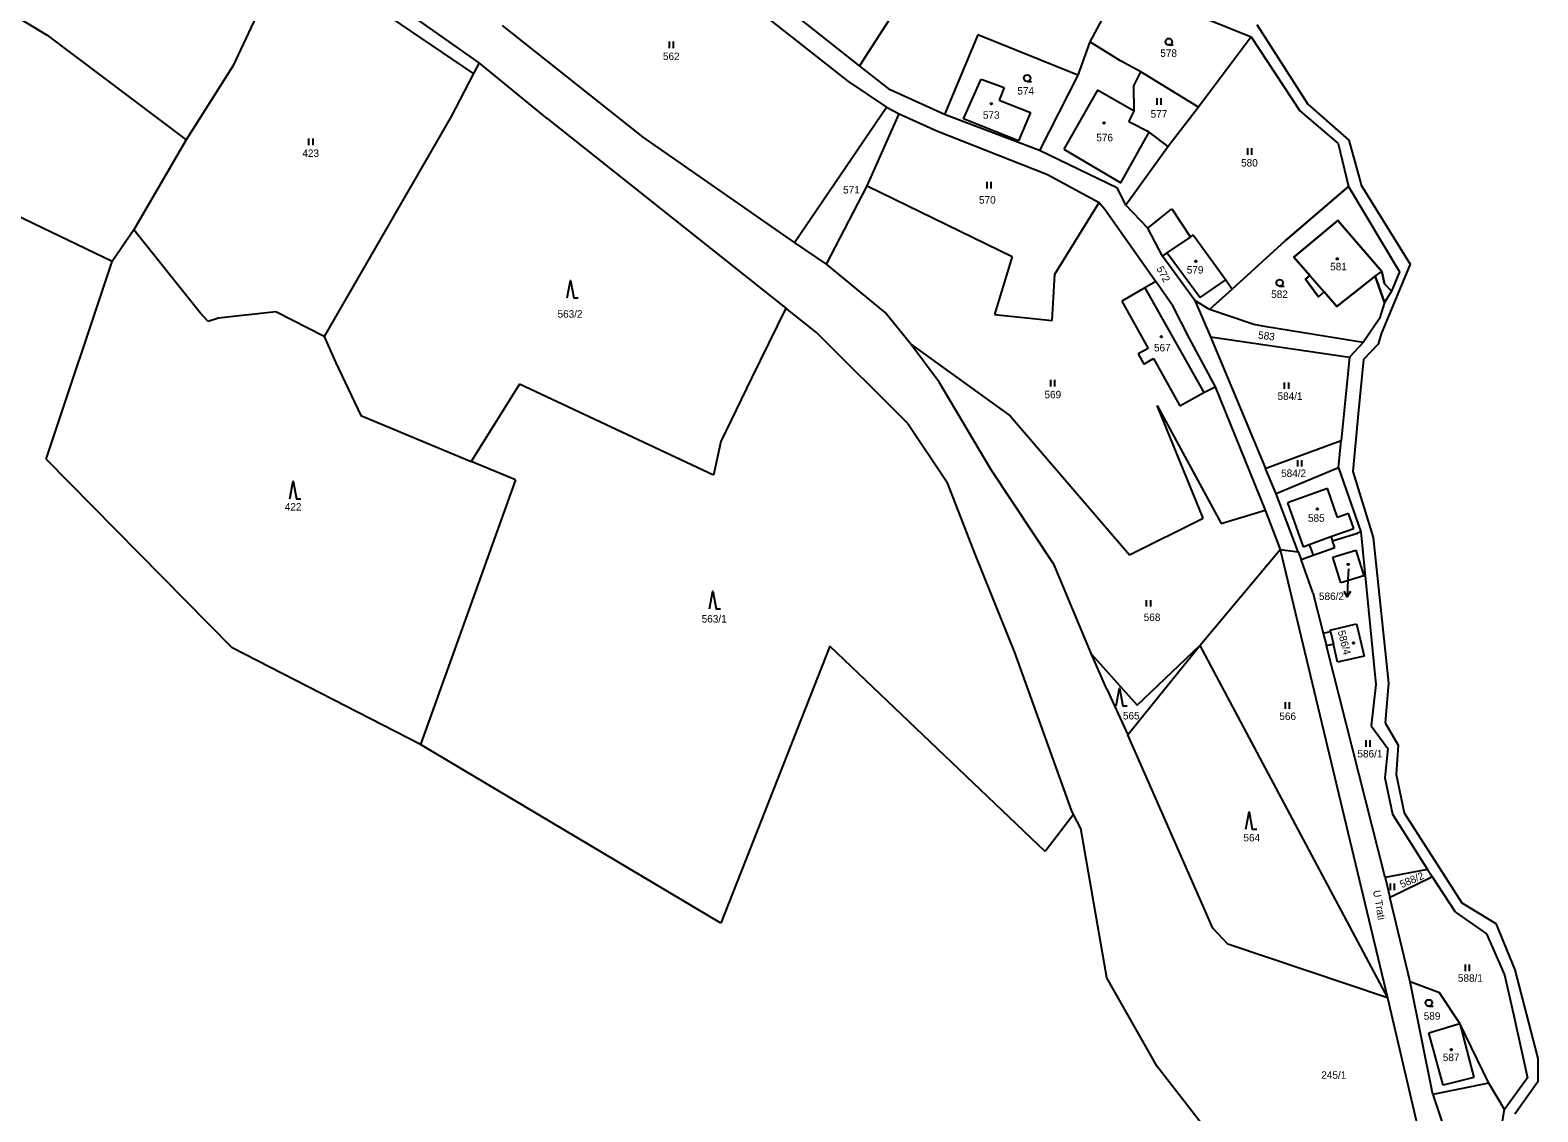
# Model space of a CAD drawing. Extents: x -670359 to -660124, y -978807 to -970072.
# Drawn here: x -668397.5 to -668054.3, y -977118.7 to -976872.6 of the extents above; entities that cross this region are included whole.
import ezdxf

# ---------------------------------------------------------------- set-up
doc = ezdxf.new("R2010")
doc.units = 0
for name, color, linetype in [('Hranice kat_území', 7, 'Continuous'), ('Hranice parcel', 7, 'Continuous'), ('Parcelní čísla', 7, 'Continuous'), ('Pop  PČ popisy', 7, 'Continuous'), ('Vnitřní kresba', 7, 'Continuous'), ('Věcná břemena k části', 7, 'Continuous'), ('Značky budov', 7, 'Continuous'), ('Značky kultur', 7, 'Continuous')]:
    doc.layers.add(name, color=color, linetype=linetype)

msp = doc.modelspace()

# ---------------------------------------------------------------- linework, layer by layer
at = {"layer": 'Hranice kat_území'}
for points in [[(-668118.31, -976871.28), (-668106.7, -976889.43)], [(-668106.7, -976889.43), (-668097.38, -976897.61)], [(-668097.38, -976897.61), (-668094.62, -976907.44)], [(-668094.62, -976907.44), (-668094.51, -976907.84)], [(-668094.51, -976907.84), (-668083.41, -976925.8)], [(-668083.41, -976925.8), (-668090.01, -976941.64)], [(-668090.68, -976944.04), (-668094.01, -976947.5)], [(-668090.01, -976941.64), (-668090.68, -976944.04)], [(-668094.01, -976947.5), (-668095.21, -976959.84)], [(-668095.21, -976959.84), (-668096.48, -976972.99)], [(-668096.48, -976972.99), (-668091.81, -976988.02)], [(-668091.81, -976988.02), (-668088.35, -977021.12)], [(-668088.35, -977021.12), (-668089.07, -977030.21)], [(-668089.07, -977030.21), (-668086.11, -977035.28)], [(-668086.11, -977035.28), (-668086.61, -977041.93)], [(-668086.61, -977041.93), (-668084.79, -977050.67)], [(-668084.79, -977050.67), (-668071.65, -977071.15)], [(-668071.65, -977071.15), (-668063.91, -977075.8)], [(-668063.91, -977075.8), (-668059.56, -977086.35)], [(-668059.56, -977086.35), (-668054.36, -977106.58)], [(-668054.36, -977106.58), (-668054.33, -977111.87)], [(-668054.33, -977111.87), (-668059.6, -977119.25)]]:
    msp.add_lwpolyline(points, dxfattribs=at)
at = {"layer": 'Hranice parcel'}
for points in [[(-668182.88, -976840.49), (-668208.77, -976880.71)], [(-668255.57, -976849.35), (-668211.38, -976884.21)], [(-668296.59, -976882.46), (-668338.97, -976853.68)], [(-668295.33, -976879.99), (-668327.45, -976857.34)], [(-668208.77, -976880.71), (-668236.32, -976858.8)], [(-668148.6, -976860.72), (-668156.29, -976875.26)], [(-668344.16, -976865.34), (-668351.37, -976880.76)], [(-668402.03, -976868.63), (-668393.67, -976873.69)], [(-668138.39, -976866.51), (-668119.61, -976874.06)], [(-668258.01, -976896.92), (-668290.02, -976871.49)], [(-668393.67, -976873.69), (-668361.98, -976897.5)], [(-668181.83, -976873.65), (-668189.39, -976891.76)], [(-668159.03, -976882.8), (-668181.83, -976873.65)], [(-668156.29, -976875.26), (-668159.03, -976882.8)], [(-668149.31, -976879.58), (-668156.29, -976875.26)], [(-668119.61, -976874.06), (-668131.6, -976890.08)], [(-668119.61, -976874.06), (-668108.48, -976890.91)], [(-668351.37, -976880.76), (-668361.98, -976897.5)], [(-668296.59, -976882.46), (-668301.67, -976892.18)], [(-668295.33, -976879.99), (-668296.59, -976882.46)], [(-668279.85, -976892.69), (-668295.33, -976879.99)], [(-668201.75, -976886.16), (-668208.77, -976880.71)], [(-668159.03, -976882.8), (-668167.74, -976899.94)], [(-668144.69, -976882.07), (-668149.31, -976879.58)], [(-668146.29, -976885.22), (-668144.69, -976882.07)], [(-668131.6, -976890.08), (-668144.69, -976882.07)], [(-668211.38, -976884.21), (-668202.61, -976890.11)], [(-668189.39, -976891.76), (-668201.75, -976886.16)], [(-668185.1, -976892.75), (-668181.07, -976883.71)], [(-668181.07, -976883.71), (-668175.79, -976885.64)], [(-668175.79, -976885.64), (-668176.94, -976888.49)], [(-668146.23, -976891), (-668146.29, -976885.22)], [(-668176.94, -976888.49), (-668169.8, -976891.27)], [(-668301.67, -976892.18), (-668330.62, -976942.26)], [(-668279.85, -976892.69), (-668225.5, -976935.79)], [(-668223.56, -976920.92), (-668202.61, -976890.11)], [(-668206.98, -976907.96), (-668199.72, -976891.57)], [(-668202.61, -976890.11), (-668199.72, -976891.57)], [(-668199.72, -976891.57), (-668191.17, -976895.49)], [(-668167.74, -976899.94), (-668189.39, -976891.76)], [(-668172.57, -976897.76), (-668185.1, -976892.75)], [(-668169.8, -976891.27), (-668172.57, -976897.76)], [(-668147.42, -976893.46), (-668146.23, -976891)], [(-668131.6, -976890.08), (-668138.45, -976899.02)], [(-668108.48, -976890.91), (-668099.79, -976898.35)], [(-668191.17, -976895.49), (-668165.95, -976905.42)], [(-668142.82, -976895.79), (-668147.42, -976893.46)], [(-668138.45, -976899.02), (-668142.82, -976895.79)], [(-668361.98, -976897.5), (-668373.88, -976918)], [(-668223.56, -976920.92), (-668258.01, -976896.92)], [(-668149.99, -976908.54), (-668167.74, -976899.94)], [(-668138.45, -976899.02), (-668148.14, -976912.37)], [(-668099.79, -976898.35), (-668097.46, -976908.16)], [(-668165.95, -976905.42), (-668154.15, -976911.81)], [(-668378.82, -976925.21), (-668414.9, -976907.91)], [(-668216.27, -976925.81), (-668206.98, -976907.96)], [(-668206.98, -976907.96), (-668174.02, -976924.07)], [(-668148.14, -976912.37), (-668149.99, -976908.54)], [(-668097.46, -976908.16), (-668111.87, -976920.52)], [(-668097.46, -976908.16), (-668085.8, -976927.59)], [(-668164.25, -976928.09), (-668154.15, -976911.81)], [(-668154.15, -976911.81), (-668152.87, -976913.28)], [(-668152.87, -976913.28), (-668141.32, -976929.77)], [(-668143.14, -976917.63), (-668148.14, -976912.37)], [(-668109.91, -976924.21), (-668099.85, -976915.9)], [(-668099.85, -976915.9), (-668089.84, -976927.46)], [(-668373.88, -976918), (-668378.82, -976925.21)], [(-668358.81, -976936.91), (-668373.88, -976918)], [(-668139.74, -976924), (-668143.14, -976917.63)], [(-668138.68, -976923.27), (-668133.43, -976919.65)], [(-668133.43, -976919.65), (-668132.75, -976919.17)], [(-668132.75, -976919.17), (-668125.38, -976929.41)], [(-668111.87, -976920.52), (-668123.89, -976931.47)], [(-668216.27, -976925.81), (-668223.56, -976920.92)], [(-668174.02, -976924.07), (-668178, -976937.29)], [(-668139.74, -976924), (-668138.68, -976923.27)], [(-668132.44, -976934.11), (-668139.74, -976924)], [(-668393.9, -976970.19), (-668378.82, -976925.21)], [(-668202.93, -976936.82), (-668216.27, -976925.81)], [(-668106.25, -976928.4), (-668109.91, -976924.21)], [(-668089.84, -976927.46), (-668089.21, -976930.29)], [(-668164.89, -976938.62), (-668164.25, -976928.09)], [(-668141.32, -976929.77), (-668143.82, -976931.22)], [(-668137.66, -976934.99), (-668141.32, -976929.77)], [(-668125.38, -976929.41), (-668123.89, -976931.47)], [(-668107.2, -976929.23), (-668106.25, -976928.4)], [(-668104.27, -976933.27), (-668107.2, -976929.23)], [(-668091.33, -976928.58), (-668100.09, -976935.47)], [(-668089.24, -976934.55), (-668091.33, -976928.58)], [(-668089.21, -976930.29), (-668087.66, -976931.97)], [(-668085.8, -976927.59), (-668087.66, -976931.97)], [(-668143.82, -976931.22), (-668149.03, -976934.24)], [(-668149.03, -976934.24), (-668143.06, -976944.99)], [(-668129.04, -976936.16), (-668132.44, -976934.11)], [(-668132.44, -976934.11), (-668128.83, -976942.33)], [(-668123.89, -976931.47), (-668129.04, -976936.16)], [(-668102.99, -976932.14), (-668104.27, -976933.27)], [(-668100.09, -976935.47), (-668102.99, -976932.14)], [(-668087.66, -976931.97), (-668089.24, -976934.55)], [(-668356.99, -976938.89), (-668358.81, -976936.91)], [(-668341.6, -976936.68), (-668354.66, -976938.07)], [(-668330.62, -976942.26), (-668341.6, -976936.68)], [(-668225.5, -976935.79), (-668233.35, -976951.76)], [(-668218.49, -976941.35), (-668225.5, -976935.79)], [(-668197.09, -976944), (-668202.93, -976936.82)], [(-668178, -976937.29), (-668164.89, -976938.62)], [(-668137.66, -976934.99), (-668133.8, -976942.54)], [(-668118.98, -976939.51), (-668129.04, -976936.16)], [(-668089.24, -976934.55), (-668090.38, -976938.14)], [(-668354.66, -976938.07), (-668356.99, -976938.89)], [(-668116.1, -976940.08), (-668118.98, -976939.51)], [(-668094.07, -976943.6), (-668116.1, -976940.08)], [(-668090.38, -976938.14), (-668094.07, -976943.6)], [(-668330.62, -976942.26), (-668327.97, -976948.26)], [(-668197.75, -976962.08), (-668218.49, -976941.35)], [(-668197.09, -976944), (-668174.41, -976960.32)], [(-668190.61, -976952.64), (-668197.09, -976944)], [(-668133.8, -976942.54), (-668127.77, -976953.72)], [(-668128.83, -976942.33), (-668097.21, -976946.95)], [(-668128.83, -976942.33), (-668116.3, -976972.3)], [(-668094.07, -976943.6), (-668097.21, -976946.95)], [(-668143.06, -976944.99), (-668145.33, -976946.25)], [(-668145.33, -976946.25), (-668144.05, -976948.57)], [(-668144.05, -976948.57), (-668141.78, -976947.31)], [(-668141.78, -976947.31), (-668135.84, -976958.02)], [(-668097.21, -976946.95), (-668099.09, -976965.9)], [(-668327.97, -976948.26), (-668322.25, -976960.28)], [(-668286.1, -976953.13), (-668297.1, -976970.69)], [(-668242, -976973.81), (-668286.1, -976953.13)], [(-668233.35, -976951.76), (-668240.31, -976966.2)], [(-668178.73, -976972.61), (-668190.61, -976952.64)], [(-668135.84, -976958.02), (-668130.38, -976954.99)], [(-668130.38, -976954.99), (-668127.77, -976953.72)], [(-668127.77, -976953.72), (-668116.39, -976981.79)], [(-668130.53, -976983.63), (-668141.01, -976957.95)], [(-668141.01, -976957.95), (-668126.38, -976984.79)], [(-668322.25, -976960.28), (-668297.1, -976970.69)], [(-668174.41, -976960.32), (-668147.28, -976991.94)], [(-668197.75, -976962.08), (-668188.67, -976975.54)], [(-668240.31, -976966.2), (-668242, -976973.81)], [(-668116.01, -976972.19), (-668101.39, -976966.76)], [(-668101.39, -976966.76), (-668099.09, -976965.9)], [(-668099.71, -976972.13), (-668099.09, -976965.9)], [(-668351.54, -977013.14), (-668393.9, -976970.19)], [(-668287.03, -976974.86), (-668297.1, -976970.69)], [(-668116.3, -976972.3), (-668116.01, -976972.19)], [(-668099.71, -976972.13), (-668113.89, -976978.07)], [(-668099.71, -976972.13), (-668094.61, -976986.71)], [(-668287.03, -976974.86), (-668308.69, -977035.11)], [(-668182.44, -976991.78), (-668188.67, -976975.54)], [(-668164.42, -976994.25), (-668178.73, -976972.61)], [(-668113.89, -976978.07), (-668116.3, -976972.3)], [(-668108.86, -976991.29), (-668113.89, -976978.07)], [(-668126.38, -976984.79), (-668116.39, -976981.79)], [(-668116.39, -976981.79), (-668113.02, -976990.77)], [(-668147.28, -976991.94), (-668130.53, -976983.63)], [(-668101.07, -976988.75), (-668095.38, -976987.03)], [(-668100.52, -976990.27), (-668101.07, -976988.75)], [(-668094.61, -976986.71), (-668095.38, -976987.03)], [(-668094.61, -976986.71), (-668091.22, -977021.43)], [(-668173.41, -977014.18), (-668182.44, -976991.78)], [(-668131.25, -977012.55), (-668113.02, -976990.77)], [(-668113.02, -976990.77), (-668088.54, -977092.78)], [(-668108.86, -976991.29), (-668108.24, -976993)], [(-668108.24, -976993), (-668105.48, -976992.03)], [(-668105.48, -976992.03), (-668100.52, -976990.27)], [(-668101.03, -976992.49), (-668095.77, -976990.88)], [(-668099.18, -976998.36), (-668101.03, -976992.49)], [(-668095.77, -976990.88), (-668093.93, -976996.72)], [(-668155.96, -977014.59), (-668164.42, -976994.25)], [(-668105.53, -977000.51), (-668108.24, -976993)], [(-668093.93, -976996.72), (-668099.18, -976998.36)], [(-668105.53, -977000.51), (-668103.19, -977009.76)], [(-668103.19, -977009.76), (-668101.54, -977009.38)], [(-668103.19, -977009.76), (-668102.46, -977012.65)], [(-668101.6, -977009.1), (-668095.59, -977007.66)], [(-668101.54, -977009.38), (-668101.6, -977009.1)], [(-668095.59, -977007.66), (-668093.9, -977014.99)], [(-668308.69, -977035.11), (-668351.54, -977013.14)], [(-668215.51, -977012.75), (-668240.29, -977075.78)], [(-668166.46, -977059.49), (-668215.51, -977012.75)], [(-668147.47, -977032.71), (-668131.25, -977012.55)], [(-668145.54, -977026.19), (-668131.25, -977012.55)], [(-668131.25, -977012.55), (-668088.54, -977092.78)], [(-668100.87, -977012.29), (-668102.46, -977012.65)], [(-668089.1, -977065.37), (-668102.46, -977012.65)], [(-668099.95, -977016.37), (-668100.87, -977012.29)], [(-668160.5, -977050.05), (-668173.41, -977014.18)], [(-668152.46, -977022.5), (-668155.96, -977014.59)], [(-668155.96, -977014.59), (-668145.54, -977026.19)], [(-668093.9, -977014.99), (-668099.95, -977016.37)], [(-668152.46, -977022.5), (-668147.65, -977032.93)], [(-668091.22, -977021.43), (-668092.3, -977030.88)], [(-668147.65, -977032.93), (-668147.47, -977032.71)], [(-668128.29, -977076.89), (-668147.65, -977032.93)], [(-668092.3, -977030.88), (-668088.45, -977036.02)], [(-668240.29, -977075.78), (-668308.69, -977035.11)], [(-668088.45, -977036.02), (-668089.19, -977042.69)], [(-668089.19, -977042.69), (-668087.42, -977050.95)], [(-668160.03, -977051.07), (-668166.46, -977059.49)], [(-668160.03, -977051.07), (-668160.5, -977050.05)], [(-668158.33, -977054.19), (-668160.03, -977051.07)], [(-668087.42, -977050.95), (-668079.47, -977063.54)], [(-668152.45, -977088.21), (-668158.33, -977054.19)], [(-668079.47, -977063.54), (-668089.1, -977065.37)], [(-668079.47, -977063.54), (-668078.4, -977065.16)], [(-668089.1, -977065.37), (-668088.02, -977069.84)], [(-668088.02, -977069.84), (-668087.66, -977069.66), (-668078.77, -977065.34), (-668078.4, -977065.16)], [(-668073.04, -977073.23), (-668078.4, -977065.16)], [(-668083.37, -977089.12), (-668088.02, -977069.84)], [(-668073.04, -977073.23), (-668065.98, -977078.19)], [(-668124.87, -977080.54), (-668128.29, -977076.89)], [(-668065.98, -977078.19), (-668061.93, -977087.49)], [(-668088.54, -977092.78), (-668124.87, -977080.54)], [(-668140.99, -977108.38), (-668152.45, -977088.21)], [(-668061.93, -977087.49), (-668059.96, -977096.13)], [(-668076.7, -977091.65), (-668083.37, -977089.12)], [(-668078.22, -977114.75), (-668083.37, -977089.12)], [(-668072.1, -977098.56), (-668076.7, -977091.65)], [(-668088.54, -977092.78), (-668077.68, -977139.18)], [(-668079.12, -977100.68), (-668072.1, -977098.56)], [(-668065.52, -977112.16), (-668072.1, -977098.56)], [(-668072.1, -977098.56), (-668068.93, -977110.85)], [(-668059.96, -977096.13), (-668056.68, -977110.99)], [(-668075.91, -977112.64), (-668079.12, -977100.68)], [(-668123.06, -977131.42), (-668140.99, -977108.38)], [(-668065.52, -977112.16), (-668078.22, -977114.75)], [(-668068.93, -977110.85), (-668075.91, -977112.64)], [(-668061.89, -977118.13), (-668065.52, -977112.16)], [(-668056.68, -977110.99), (-668061.89, -977118.13)], [(-668078.22, -977114.75), (-668072.32, -977132.41)], [(-668063.71, -977128.95), (-668061.89, -977118.13)]]:
    msp.add_lwpolyline(points, dxfattribs=at)
at = {"layer": 'Parcelní čísla'}
for p, q in [((-668097.44, -976995.12), (-668097.56, -976997.53)), ((-668096.95, -977000.26), (-668097.76, -977001.53))]:
    msp.add_line(p, q, dxfattribs=at)
msp.add_lwpolyline([(-668097.56, -976997.53), (-668097.76, -977001.53), (-668098.44, -977000.19)], dxfattribs=at)
at = {"layer": 'Vnitřní kresba'}
for points in [[(-668154.55, -976886.26), (-668162.22, -976899.63)], [(-668146.23, -976891), (-668154.55, -976886.26)], [(-668149.24, -976907.34), (-668142.82, -976895.79)], [(-668162.22, -976899.63), (-668149.24, -976907.34)], [(-668143.14, -976917.63), (-668137.65, -976913.26)], [(-668137.65, -976913.26), (-668133.43, -976919.65)], [(-668138.68, -976923.27), (-668131.19, -976933.41)], [(-668091.33, -976928.58), (-668089.84, -976927.46)], [(-668131.19, -976933.41), (-668125.38, -976929.41)], [(-668106.25, -976928.4), (-668102.99, -976932.14)], [(-668143.82, -976931.22), (-668130.38, -976954.99)], [(-668102.23, -976976.89), (-668111.32, -976980.14)], [(-668099.9, -976983.45), (-668102.23, -976976.89)], [(-668111.32, -976980.14), (-668107.78, -976990.1)], [(-668097.43, -976982.57), (-668099.9, -976983.45)], [(-668096.23, -976985.93), (-668097.43, -976982.57)], [(-668106.37, -976989.59), (-668101.42, -976987.8)], [(-668101.42, -976987.8), (-668096.23, -976985.93)], [(-668101.42, -976987.8), (-668101.07, -976988.75)], [(-668113.02, -976990.77), (-668108.86, -976991.29)], [(-668107.78, -976990.1), (-668106.37, -976989.59)], [(-668106.37, -976989.59), (-668105.48, -976992.03)], [(-668101.54, -977009.38), (-668100.87, -977012.29)]]:
    msp.add_lwpolyline(points, dxfattribs=at)
at = {"layer": 'Věcná břemena k části'}
msp.add_lwpolyline([(-668129.04, -976936.16), (-668123.89, -976931.47), (-668111.87, -976920.52), (-668097.46, -976908.16), (-668085.8, -976927.59), (-668087.66, -976931.97), (-668089.21, -976930.29), (-668089.84, -976927.46), (-668099.85, -976915.9), (-668109.91, -976924.21), (-668106.25, -976928.4), (-668107.2, -976929.23), (-668104.27, -976933.27), (-668102.99, -976932.14), (-668100.09, -976935.47), (-668091.33, -976928.58), (-668089.24, -976934.55), (-668090.38, -976938.14), (-668094.07, -976943.6), (-668116.1, -976940.08), (-668118.98, -976939.51), (-668129.04, -976936.16)], dxfattribs=at)
at = {"layer": 'Značky budov'}
for centre in [(-668178.73, -976889.32), (-668153.06, -976893.71), (-668132.18, -976925.19), (-668099.99, -976924.61), (-668140.02, -976942.31), (-668104.53, -976981.52), (-668097.51, -976994.14), (-668096.29, -977012.03), (-668074.04, -977104.55)]:
    msp.add_circle(centre, 0.175, dxfattribs=at)
at = {"layer": 'Značky kultur'}
for p, q in [((-668252.05, -976875.17), (-668252.05, -976876.67)), ((-668251.05, -976876.67), (-668251.05, -976875.17)), ((-668138.33, -976875.94), (-668137.33, -976875.94)), ((-668170.57, -976884.27), (-668169.57, -976884.27)), ((-668141.04, -976888.03), (-668141.04, -976889.53)), ((-668140.04, -976889.53), (-668140.04, -976888.03)), ((-668334.13, -976897.21), (-668334.13, -976898.71)), ((-668333.13, -976898.71), (-668333.13, -976897.21)), ((-668120.45, -976899.4), (-668120.45, -976900.9)), ((-668119.45, -976900.9), (-668119.45, -976899.4)), ((-668179.74, -976907.11), (-668179.74, -976908.61)), ((-668178.74, -976908.61), (-668178.74, -976907.11)), ((-668113.1, -976930.8), (-668112.1, -976930.8)), ((-668165.24, -976952.13), (-668165.24, -976953.63)), ((-668164.24, -976953.63), (-668164.24, -976952.13)), ((-668112.04, -976952.71), (-668112.04, -976954.21)), ((-668111.04, -976954.21), (-668111.04, -976952.71)), ((-668109.04, -976970.38), (-668109.04, -976971.88)), ((-668108.04, -976971.88), (-668108.04, -976970.38)), ((-668143.45, -977002.24), (-668143.45, -977003.74)), ((-668142.45, -977003.74), (-668142.45, -977002.24)), ((-668111.85, -977025.49), (-668111.85, -977026.99)), ((-668110.85, -977026.99), (-668110.85, -977025.49)), ((-668093.48, -977034.14), (-668093.48, -977035.64)), ((-668092.48, -977035.64), (-668092.48, -977034.14)), ((-668087.96, -977066.72), (-668087.96, -977068.22)), ((-668086.96, -977068.22), (-668086.96, -977066.72)), ((-668070.88, -977085.16), (-668070.88, -977086.66)), ((-668069.88, -977086.66), (-668069.88, -977085.16)), ((-668079.14, -977094.67), (-668078.14, -977094.67))]:
    msp.add_line(p, q, dxfattribs=at)
for points in [[(-668275.29, -976933.5), (-668274.54, -976929.5), (-668273.79, -976933.5), (-668272.79, -976933.5)], [(-668338.38, -976979.18), (-668337.63, -976975.18), (-668336.88, -976979.18), (-668335.88, -976979.18)], [(-668242.87, -977004.23), (-668242.12, -977000.23), (-668241.37, -977004.23), (-668240.37, -977004.23)], [(-668150.28, -977026.29), (-668149.53, -977022.29), (-668148.78, -977026.29), (-668147.78, -977026.29)], [(-668120.82, -977054.41), (-668120.07, -977050.41), (-668119.32, -977054.41), (-668118.32, -977054.41)]]:
    msp.add_lwpolyline(points, dxfattribs=at)
for centre, radius in [((-668138.33, -976875.19), 0.75), ((-668170.57, -976883.52), 0.75), ((-668178.73, -976889.32), 0.175), ((-668153.06, -976893.71), 0.175), ((-668132.18, -976925.19), 0.175), ((-668099.99, -976924.61), 0.175), ((-668113.1, -976930.05), 0.75), ((-668140.02, -976942.31), 0.175), ((-668104.53, -976981.52), 0.175), ((-668097.51, -976994.14), 0.175), ((-668096.29, -977012.03), 0.175), ((-668079.14, -977093.92), 0.75), ((-668074.04, -977104.55), 0.175)]:
    msp.add_circle(centre, radius, dxfattribs=at)

# ---------------------------------------------------------------- texts
at = {"layer": 'Parcelní čísla'}
for s, height, p in [('562', 1.7, (-668253.48, -976879.37)), ('578', 1.7, (-668140.26, -976878.64)), ('574', 1.7, (-668172.8, -976887.22)), ('573', 1.7, (-668180.65, -976892.72)), ('577', 1.7, (-668142.47, -976892.47)), ('576', 1.7, (-668154.83, -976897.85)), ('423', 1.7, (-668335.56, -976901.41)), ('580', 1.7, (-668121.88, -976903.6)), ('571', 1.7, (-668212.47, -976909.73)), ('570', 1.7, (-668181.53, -976912.04)), ('579', 1.7, (-668134.24, -976927.95)), ('581', 1.7, (-668101.6, -976927.21)), ('582', 1.7, (-668115.03, -976933.5)), ('563/2', 1.7, (-668277.47, -976937.99)), ('567', 1.7, (-668141.7, -976945.67)), ('569', 1.7, (-668166.63, -976956.33)), ('584/1', 1.7, (-668113.58, -976956.7)), ('584/2', 1.7, (-668112.77, -976974.24)), ('422', 1.7, (-668339.56, -976981.88)), ('585', 1.7, (-668106.65, -976984.43)), ('586/2', 0.1, (-668097.44, -976995.12)), ('586/2', 1.7, (-668104.15, -977002.23)), ('563/1', 1.7, (-668244.66, -977007.36)), ('568', 1.7, (-668144.04, -977007.01)), ('565', 1.7, (-668148.77, -977029.41)), ('566', 1.7, (-668113.17, -977029.53)), ('586/1', 1.7, (-668095.39, -977038.05)), ('564', 1.7, (-668121.34, -977057.14)), ('588/1', 1.7, (-668072.53, -977089.09)), ('589', 1.7, (-668080.3, -977097.73)), ('587', 1.7, (-668075.97, -977107.15)), ('245/1', 1.7, (-668103.62, -977111.16))]:
    msp.add_text(s, height=height, dxfattribs=at).set_placement(p)
for s, rotation, p in [('572', 298.6707, (-668141.22, -976926.83)), ('583', 352.3651, (-668118.09, -976942.72)), ('586/4', 284.3493, (-668099.9, -977009.36)), ('588/2', 22.7782, (-668085.32, -977067.8))]:
    msp.add_text(s, height=1.7, rotation=rotation, dxfattribs=at).set_placement(p)
at = {"layer": 'Pop  PČ popisy'}
msp.add_text('U Trati', height=1.7, rotation=280.1621, dxfattribs=at).set_placement((-668091.87, -977068.42))

doc.saveas('drawing.dxf')
